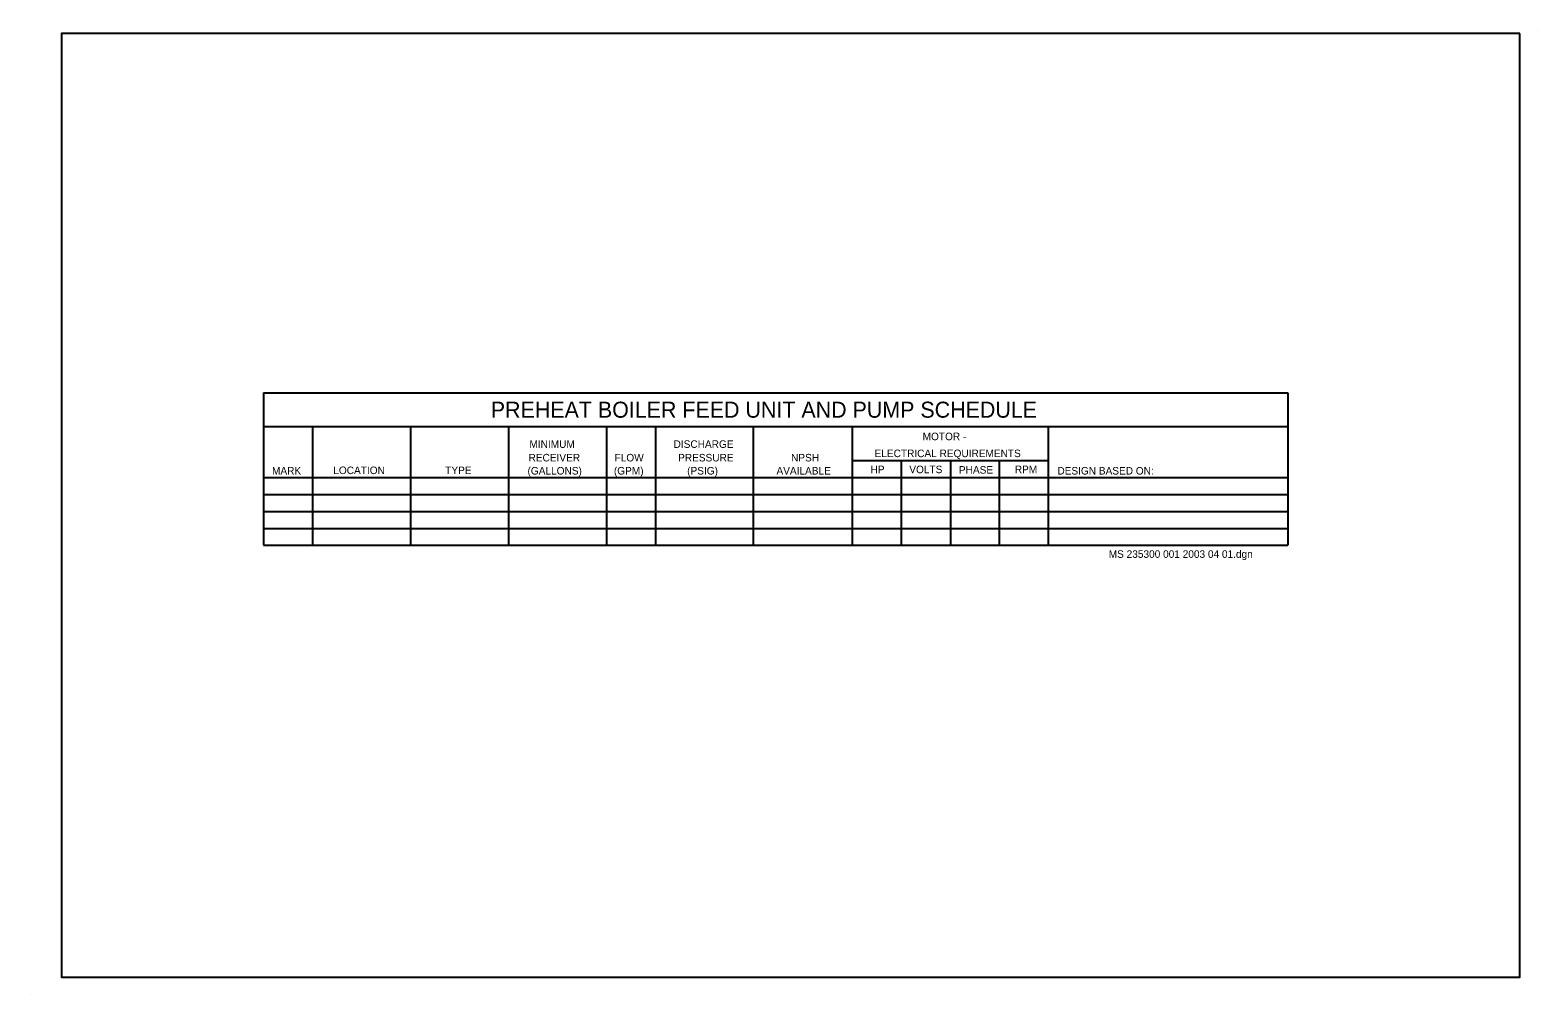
# Model space of a CAD drawing. Extents: x 10239 to 10373, y 10272 to 10357.
import ezdxf

# ---------------------------------------------------------------- set-up
doc = ezdxf.new("R2010")
doc.units = 0
for name, color, linetype in [('G-ANNO-PD', 7, 'Continuous'), ('G-ANNO-TEXT', 7, 'Continuous'), ('G-DETL-GRID', 7, 'Continuous'), ('G-SCHD-LINE', 7, 'Continuous'), ('M-HOTW-PIPE', 7, 'Continuous'), ('M-MKUP-DUCT-N', 7, 'Continuous')]:
    doc.layers.add(name, color=color, linetype=linetype)

msp = doc.modelspace()

# ---------------------------------------------------------------- linework, layer by layer
at = {"layer": 'G-ANNO-PD'}
for p, q in [((10372.64, 10357.49), (10372.64, 10357.49)), ((10239.28, 10272.13), (10239.28, 10272.13))]:
    msp.add_line(p, q, dxfattribs=at)
at = {"layer": 'G-DETL-GRID'}
msp.add_lwpolyline([(10371.03, 10357.19), (10242.05, 10357.19), (10242.05, 10273.71), (10371.03, 10273.71)], close=True, dxfattribs=at)
at = {"layer": 'G-SCHD-LINE'}
for p, q in [((10259.92, 10325.41), (10350.53, 10325.41)), ((10259.92, 10325.41), (10259.92, 10311.91)), ((10350.53, 10325.41), (10350.53, 10311.91)), ((10259.92, 10322.41), (10350.53, 10322.41)), ((10312, 10319.41), (10329.33, 10319.41)), ((10259.92, 10317.91), (10350.53, 10317.91)), ((10259.92, 10311.91), (10350.53, 10311.91))]:
    msp.add_line(p, q, dxfattribs=at)
at = {"layer": 'M-MKUP-DUCT-N'}
for p, q in [((10264.26, 10322.41), (10264.26, 10317.91)), ((10272.92, 10322.41), (10272.92, 10317.91)), ((10281.59, 10322.41), (10281.59, 10317.91)), ((10290.26, 10322.41), (10290.26, 10317.91)), ((10294.59, 10322.41), (10294.59, 10317.91)), ((10303.23, 10322.41), (10303.23, 10311.91)), ((10312, 10322.41), (10312, 10317.91)), ((10329.33, 10322.41), (10329.33, 10317.91)), ((10316.33, 10319.41), (10316.33, 10317.91)), ((10320.67, 10319.41), (10320.67, 10317.91)), ((10325, 10319.41), (10325, 10317.91)), ((10264.26, 10317.91), (10264.26, 10311.91)), ((10272.92, 10317.91), (10272.92, 10311.91)), ((10281.59, 10317.91), (10281.59, 10311.91)), ((10290.26, 10317.91), (10290.26, 10311.91)), ((10294.59, 10317.91), (10294.59, 10311.91)), ((10312, 10317.91), (10312, 10311.91)), ((10316.33, 10317.91), (10316.33, 10311.91)), ((10320.67, 10317.91), (10320.67, 10311.91)), ((10325, 10317.91), (10325, 10311.91)), ((10329.33, 10317.91), (10329.33, 10311.91)), ((10259.92, 10316.41), (10350.53, 10316.41)), ((10259.92, 10314.91), (10350.53, 10314.91)), ((10259.92, 10313.41), (10350.53, 10313.41))]:
    msp.add_line(p, q, dxfattribs=at)

# ---------------------------------------------------------------- texts
at = {"layer": 'G-ANNO-TEXT'}
msp.add_text('MS 235300 001 2003 04 01.dgn', height=0.6667, dxfattribs=at).set_placement((10334.68, 10310.8))
at = {"layer": 'M-HOTW-PIPE'}
for s, height, p in [('PREHEAT BOILER FEED UNIT AND PUMP SCHEDULE', 1.4167, (10280.02, 10323.2)), ('MINIMUM', 0.667, (10283.44, 10320.53)), ('DISCHARGE', 0.667, (10296.19, 10320.53)), ('MOTOR -', 0.667, (10318.22, 10321.21)), ('RECEIVER', 0.667, (10283.36, 10319.33)), ('FLOW', 0.667, (10290.97, 10319.33)), ('PRESSURE', 0.667, (10296.59, 10319.33)), ('NPSH', 0.667, (10306.58, 10319.33)), ('ELECTRICAL REQUIREMENTS', 0.6667, (10313.97, 10319.71)), ('MARK', 0.667, (10260.67, 10318.17)), ('LOCATION', 0.667, (10266.09, 10318.21)), ('TYPE', 0.667, (10275.99, 10318.21)), ('(GALLONS)', 0.667, (10283.27, 10318.17)), ('(GPM)', 0.667, (10290.91, 10318.17)), ('(PSIG)', 0.667, (10297.39, 10318.17)), ('AVAILABLE', 0.667, (10305.29, 10318.17)), ('HP', 0.667, (10313.61, 10318.29)), ('VOLTS', 0.667, (10317.04, 10318.29)), ('PHASE', 0.667, (10321.43, 10318.25)), ('RPM', 0.667, (10326.37, 10318.29)), ('DESIGN BASED ON:', 0.6667, (10330.14, 10318.17))]:
    msp.add_text(s, height=height, dxfattribs=at).set_placement(p)

doc.saveas('drawing.dxf')
